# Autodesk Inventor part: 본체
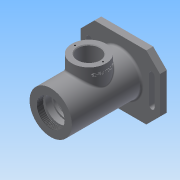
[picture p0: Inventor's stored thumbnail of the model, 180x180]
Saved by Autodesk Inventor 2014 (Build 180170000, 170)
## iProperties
Created: 2017-10
Part Number: 본체
Material: 일반
Document SubType Name: Modeling
Designer: net
Density: 1 g/cm^3
Appearance: 기본값
Mass: 273.306 g
Surface Area: 656.095 cm^2
Volume: 273.306 cm^3
Author: net
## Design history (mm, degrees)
sketch "스케치1"
  geometry: L1 (-58, 47)-(58, 47); L2 (58, 47)-(58, -47); L3 (58, -47)-(-58, -47); L4 (-58, -47)-(-58, 47); 3 further points
  constraints: 8 end point, 2 midpoint, 2 parallel, 1 horizontal, 1 horizontal alignment, 1 perpendicular, 1 vertical alignment
  dimensions: "d1" = 94 distance of L1.end L2.end; "d2" = 116 distance of L2.end L3.end
extrude "돌출1" new body sketch "스케치1" distance "d3" = 10; taper "d4" = 0 deg
sketch "스케치2"
  geometry: C1 r 35 at (0, 0); 1 further point
  constraints: 1 centre point, 1 coincident
  dimensions: "d5" = 70 diameter of C1
extrude "돌출2" join sketch "스케치2" distance "d6" = 3; taper "d7" = 0 deg
sketch "스케치3"
  geometry: C1 r 31 at (0, 0); 1 further point
  constraints: 1 centre point, 1 coincident
  dimensions: "d8" = 62 diameter of C1
extrude "돌출3" join sketch "스케치3" distance "d9" = 102; taper "d10" = 0 deg
sketch "스케치4"
  geometry: L1 (-31, -102)-(31, -102) reference; L2 (31, 0)-(-31, 0) reference; L3 (-47, 0)-(47, 0) reference; L4 (-47, 0)-(-47, 10) reference; L5 (47, 10)-(-47, 10) reference; L6 (47, 0)-(47, 10) reference; L7 (-35, 10)-(35, 10) reference; L8 (35, 13)-(-35, 13) reference; L9 (0, 13)-(0, -102); L10 (0, -93)-(-24, -93); L11 (-24, -93)-(-24, -90); L12 (-24, -90)-(-20, -90); L13 (-20, -90)-(-20, -81); L14 (-20, -81)-(-17.5, -81); L15 (-17.5, -81)-(-17.5, -77.75); L16 (-17.5, -77.75)-(-18.5, -77.75); L17 (-18.5, -77.75)-(-18.5, -76); L18 (-18.5, -76)-(-17.5, -76); L19 (-17.5, -76)-(-17.5, -65); L20 (-17.5, -65)-(-26, -65); L21 (-26, -65)-(-26, -27); L22 (-26, -27)-(-17.5, -27); L23 (-17.5, -27)-(-17.5, -16); L24 (-17.5, -16)-(-16.5, -16); L25 (-16.5, -16)-(-16.5, -11); L26 (-16.5, -11)-(-10, -11); L27 (-10, -11)-(-10, -8.3); L28 (-10, -8.3)-(-12.5, -8.3); L29 (-12.5, -8.3)-(-12.5, -1); L30 (-12.5, -1)-(-16, -1); L31 (-16, -1)-(-22, 13); 1 further point
  constraints: 46 end point, 14 parallel, 3 collinear, 2 midpoint, 2 perpendicular, 2 point on line
  dimensions: "d12" = 3 distance of L10.end L11.end; "d13" = 21 distance between parallel lines of L14 L1; "d14" = 26 distance between parallel lines of L1 L18; "d15" = 60 distance between parallel lines of L24 L18; "d16" = 38 distance of L20.end L21.end; "d18" = 14 distance between parallel lines of L30 L8; "d19" = 12 distance between parallel lines of L1 L12; "d20" = 48 diameter of L11 L9; "d21" = 40 diameter of L13 L9; "d23" = 35 diameter of L15 L9; "d24" = 11 distance of L22.end L23.end; "d25" = 35 diameter of L19 L9; "d26" = 52 diameter of L21 L9; "d27" = 37 diameter of L17 L9; "d28" = 1.75 distance of L16.end L17.end; "d30" = 5 distance of L24.end L25.end; "d31" = 2.7 distance of L26.end L27.end; "d32" = 25 diameter of L29 L9; "d33" = 20 diameter of L27 L9; "d34" = 33 diameter of L25 L9; "d35" = 32 diameter of L30.end L9; "d36" = 44 diameter of L31.end L9
revolve "회전1" sketch "스케치4" stored, may be unused: angle "d37" = 90 deg
hole "구멍1" diameter "d40" = 40.376; stored, may be unused: countersink angle "d44" = 90 deg, drill point angle "d46" = 0 deg; dims "d38" = 10, "d39" = 10, "d41" = 9, "d42" = 4, "d43" = 2, "d45" = 9
sketch "스케치5"
  geometry: L1 (0, 0)-(116, 0) reference; L2 (89, 102)-(27, 102) reference; L3 (27, 0)-(89, 0) reference; L4 (0, 0)-(116, 0) reference; L5 (0, 0)-(0, -10) reference; L6 (116, -10)-(0, -10) reference; L7 (116, 0)-(116, -10) reference; C1 r 25 at (58, 46); 2 further points
  constraints: 1 centre point, 1 midpoint, 1 vertical alignment
  dimensions: "d47" = 50 diameter of C1; "d48" = 56 distance from line of C1.centre L2
extrude "돌출4" join sketch "스케치5" stored distance "d49" = 102; taper "d50" = 0 deg
hole "구멍2" diameter "d53" = 32; stored, may be unused: countersink angle "d57" = 90 deg, drill point angle "d59" = 0 deg; dims "d51" = 10, "d52" = 10, "d54" = 9, "d55" = 4, "d56" = 2, "d58" = 47
sketch "스케치6"
  geometry: L1 (-58, 47)-(-58, -47) reference; L2 (-46, 20)-(-46, -20); L3 (-50, 20)-(-50, -20); L4 (-42, -20)-(-42, 20); L5 (46, 20)-(46, -20); L6 (42, 20)-(42, -20); L7 (50, -20)-(50, 20); C1 r 35 at (0, 0) reference; A1 r 4 centre (-46, 20) between (-42, 20) and (-50, 20); A2 r 4 centre (-46, -20) between (-50, -20) and (-42, -20); A3 r 4 centre (46, 20) between (50, 20) and (42, 20); A4 r 4 centre (46, -20) between (42, -20) and (50, -20); 2 further points
  constraints: 16 end point, 8 point on circle, 8 tangent, 5 parallel, 4 centre point, 3 horizontal alignment, 2 midpoint, 1 equal radius
  dimensions: "d60" = 40 distance of L2.start L2.end; "d61" = 4 radius of A1; "d62" = 46 distance from line of L2 C1.centre; "d63" = 46 distance from line of L5 C1.centre
extrude "돌출5" cut sketch "스케치6" stored distance "d64" = 102; taper "d65" = 0 deg
chamfer "모따기1" distance "d66" = 20; stored, may be unused: second distance "d67" = 2, angle "d68" = 45 deg
node "작업 평면1"
sketch "스케치7"
  geometry: L1 (0, -25)-(0, 25) reference; L2 (16, -56)-(78, -56) reference; 2 further points
  constraints: 1 other
  dimensions: "d69" = 10 distance from line of point (10, 0) L1; "d70" = 56 distance from line of L2 point (10, 0)
feature "엠보싱1" sketch "스케치7" dims "d1" = 94, "d2" = 116, "d71" = 0.5, "d72" = 0
sketch "스케치8"
  geometry: C1 r 16 at (0, 0) reference; 2 further points
  constraints: 1 horizontal alignment
  dimensions: "d73" = 20.5 distance of C1.centre point (20.5, 0)
hole "구멍3" sketch "스케치8" at (20.5, 0) diameter "d74" = 2.459; stored, may be unused: countersink angle "d78" = 90 deg, drill point angle "d80" = 118 deg; dims "d75" = 6, "d76" = 4, "d77" = 2, "d79" = 8
chamfer "모따기2" distance "d84" = 0.7; stored, may be unused: second distance "d85" = 2, angle "d86" = 30 deg
chamfer "모따기3" distance "d87" = 1; stored, may be unused: second distance "d88" = 2, angle "d89" = 30 deg
fillet "모깎기1" dims "d90" = 0.3
fillet "모깎기2" dims "d91" = 0.3
fillet "모깎기3" dims "d92" = 3
fillet "모깎기4" dims "d93" = 3
fillet "모깎기5" dims "d94" = 3
node "솔리드1"
pattern_circular "원형 패턴1" dims angle "d82" = 360 deg
node "투영된 루프1"
node "투영된 루프2"
node "투영된 루프3"
node "투영된 루프4"
